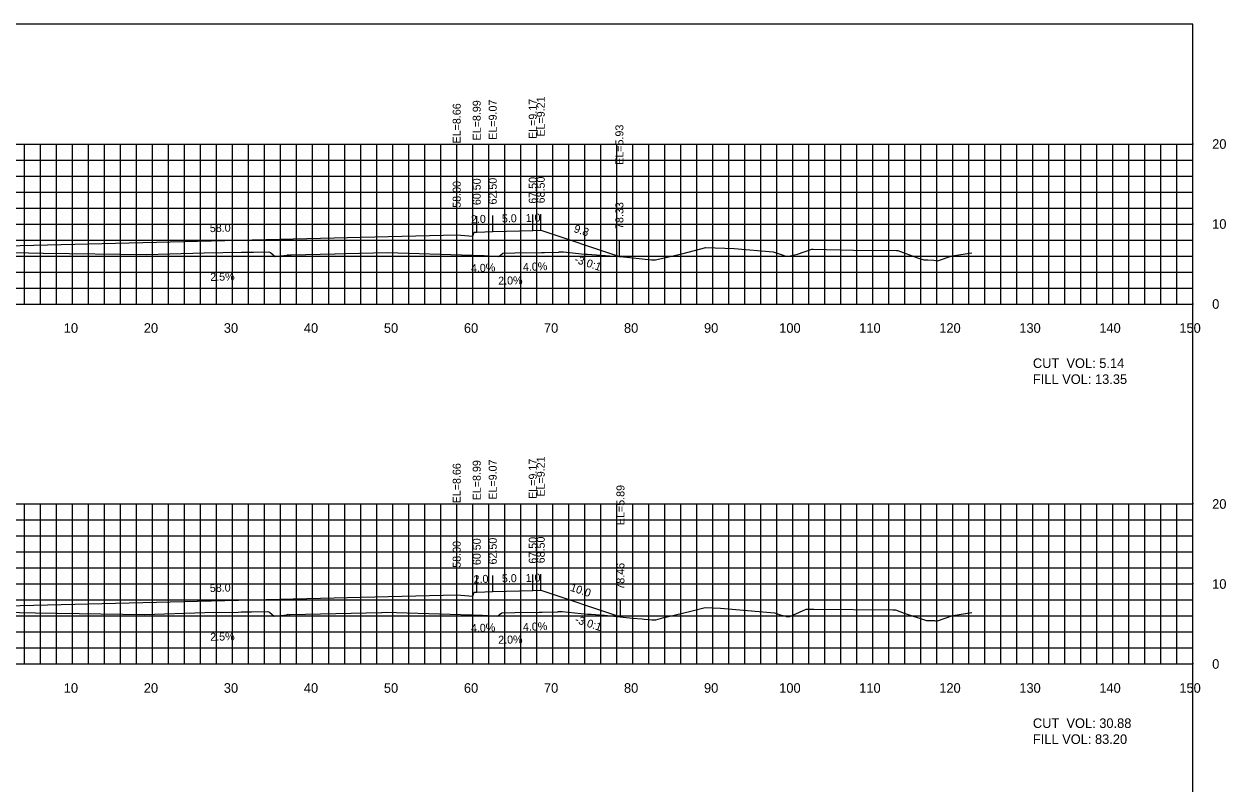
# Model space of a CAD drawing. Extents: x 1797419 to 1809236, y 248759 to 251512.
# Drawn here: x 1807054.9 to 1807205.1, y 250949.9 to 251044.9 of the extents above; entities that cross this region are included whole.
import ezdxf

# ---------------------------------------------------------------- set-up
doc = ezdxf.new("R2010")
doc.units = 0
for name, color, linetype in [('10', 7, 'Continuous'), ('3', 7, 'Continuous'), ('31', 7, 'Continuous'), ('4', 7, 'Continuous'), ('60', 7, 'Continuous'), ('ANNO-TXT', 7, 'Continuous'), ('CL-CNST', 7, 'Continuous'), ('Level 62', 7, 'Continuous'), ('M-ROADS', 7, 'Continuous')]:
    doc.layers.add(name, color=color, linetype=linetype)

msp = doc.modelspace()

# ---------------------------------------------------------------- linework, layer by layer
for p, q in [((1807109, 251018.55), (1807109, 251020.55)), ((1807111.5, 251018.88), (1807111.5, 251020.88)), ((1807113.5, 251018.96), (1807113.5, 251020.96)), ((1807118.5, 251019.06), (1807118.5, 251021.06)), ((1807119.5, 251019.1), (1807119.5, 251021.1)), ((1807129.33, 251015.82), (1807129.33, 251017.82)), ((1807109, 250973.55), (1807109, 250975.55)), ((1807111.5, 250973.88), (1807111.5, 250975.88)), ((1807113.5, 250973.96), (1807113.5, 250975.96)), ((1807118.5, 250974.06), (1807118.5, 250976.06)), ((1807119.5, 250974.1), (1807119.5, 250976.1)), ((1807129.46, 250970.78), (1807129.46, 250972.78))]:
    msp.add_line(p, q)
msp.add_lwpolyline([(1806901, 250854.89), (1807201, 250854.89), (1807201, 251044.89), (1806901, 251044.89)], close=True)
at = {"layer": '60'}
for p, q in [((1807201, 251009.89), (1807201, 251029.89)), ((1807201.06, 251029.89), (1807201, 251029.89)), ((1807201.06, 251019.89), (1807201, 251019.89)), ((1806901, 251009.89), (1807201, 251009.89)), ((1807061, 251009.83), (1807061, 251009.89)), ((1807071, 251009.83), (1807071, 251009.89)), ((1807081, 251009.83), (1807081, 251009.89)), ((1807091, 251009.83), (1807091, 251009.89)), ((1807101, 251009.83), (1807101, 251009.89)), ((1807111, 251009.83), (1807111, 251009.89)), ((1807121, 251009.83), (1807121, 251009.89)), ((1807131, 251009.83), (1807131, 251009.89)), ((1807141, 251009.83), (1807141, 251009.89)), ((1807151, 251009.83), (1807151, 251009.89)), ((1807161, 251009.83), (1807161, 251009.89)), ((1807171, 251009.83), (1807171, 251009.89)), ((1807181, 251009.83), (1807181, 251009.89)), ((1807191, 251009.83), (1807191, 251009.89)), ((1807201, 251009.83), (1807201, 251009.89)), ((1807201.06, 251009.89), (1807201, 251009.89)), ((1807201, 250964.89), (1807201, 250984.89)), ((1807201.06, 250984.89), (1807201, 250984.89)), ((1807201.06, 250974.89), (1807201, 250974.89)), ((1806901, 250964.89), (1807201, 250964.89)), ((1807061, 250964.83), (1807061, 250964.89)), ((1807071, 250964.83), (1807071, 250964.89)), ((1807081, 250964.83), (1807081, 250964.89)), ((1807091, 250964.83), (1807091, 250964.89)), ((1807101, 250964.83), (1807101, 250964.89)), ((1807111, 250964.83), (1807111, 250964.89)), ((1807121, 250964.83), (1807121, 250964.89)), ((1807131, 250964.83), (1807131, 250964.89)), ((1807141, 250964.83), (1807141, 250964.89)), ((1807151, 250964.83), (1807151, 250964.89)), ((1807161, 250964.83), (1807161, 250964.89)), ((1807171, 250964.83), (1807171, 250964.89)), ((1807181, 250964.83), (1807181, 250964.89)), ((1807191, 250964.83), (1807191, 250964.89)), ((1807201, 250964.83), (1807201, 250964.89)), ((1807201.06, 250964.89), (1807201, 250964.89))]:
    msp.add_line(p, q, dxfattribs=at)
at = {"layer": 'CL-CNST'}
for points in [[(1806978.72, 251017.46), (1806982.5, 251016.2), (1806983.5, 251016.16), (1806988.5, 251016.06), (1806990.5, 251015.98), (1806990.83, 251015.98), (1806991, 251015.48), (1806993, 251015.65), (1807051, 251017.1), (1807109, 251018.55), (1807111, 251018.38), (1807111.17, 251018.88), (1807111.5, 251018.88), (1807113.5, 251018.96), (1807118.5, 251019.06), (1807119.5, 251019.1), (1807129.33, 251015.82)], [(1806978.78, 250972.44), (1806982.5, 250971.2), (1806983.5, 250971.16), (1806988.5, 250971.06), (1806990.5, 250970.98), (1806990.83, 250970.98), (1806991, 250970.48), (1806993, 250970.65), (1807051, 250972.1), (1807109, 250973.55), (1807111, 250973.38), (1807111.17, 250973.88), (1807111.5, 250973.88), (1807113.5, 250973.96), (1807118.5, 250974.06), (1807119.5, 250974.1), (1807129.46, 250970.78)]]:
    msp.add_lwpolyline(points, dxfattribs=at)
at = {"layer": 'Level 62'}
for p, q in [((1806901, 251029.89), (1807201, 251029.89)), ((1807055, 251009.89), (1807055, 251029.89)), ((1807057, 251009.89), (1807057, 251029.89)), ((1807059, 251009.89), (1807059, 251029.89)), ((1807061, 251009.89), (1807061, 251029.89)), ((1807063, 251009.89), (1807063, 251029.89)), ((1807065, 251009.89), (1807065, 251029.89)), ((1807067, 251009.89), (1807067, 251029.89)), ((1807069, 251009.89), (1807069, 251029.89)), ((1807071, 251009.89), (1807071, 251029.89)), ((1807073, 251009.89), (1807073, 251029.89)), ((1807075, 251009.89), (1807075, 251029.89)), ((1807077, 251009.89), (1807077, 251029.89)), ((1807079, 251009.89), (1807079, 251029.89)), ((1807081, 251009.89), (1807081, 251029.89)), ((1807083, 251009.89), (1807083, 251029.89)), ((1807085, 251009.89), (1807085, 251029.89)), ((1807087, 251009.89), (1807087, 251029.89)), ((1807089, 251009.89), (1807089, 251029.89)), ((1807091, 251009.89), (1807091, 251029.89)), ((1807093, 251009.89), (1807093, 251029.89)), ((1807095, 251009.89), (1807095, 251029.89)), ((1807097, 251009.89), (1807097, 251029.89)), ((1807099, 251009.89), (1807099, 251029.89)), ((1807101, 251009.89), (1807101, 251029.89)), ((1807103, 251009.89), (1807103, 251029.89)), ((1807105, 251009.89), (1807105, 251029.89)), ((1807107, 251009.89), (1807107, 251029.89)), ((1807109, 251009.89), (1807109, 251029.89)), ((1807111, 251009.89), (1807111, 251029.89)), ((1807113, 251009.89), (1807113, 251029.89)), ((1807115, 251009.89), (1807115, 251029.89)), ((1807117, 251009.89), (1807117, 251029.89)), ((1807119, 251009.89), (1807119, 251029.89)), ((1807121, 251009.89), (1807121, 251029.89)), ((1807123, 251009.89), (1807123, 251029.89)), ((1807125, 251009.89), (1807125, 251029.89)), ((1807127, 251009.89), (1807127, 251029.89)), ((1807129, 251009.89), (1807129, 251029.89)), ((1807131, 251009.89), (1807131, 251029.89)), ((1807133, 251009.89), (1807133, 251029.89)), ((1807135, 251009.89), (1807135, 251029.89)), ((1807137, 251009.89), (1807137, 251029.89)), ((1807139, 251009.89), (1807139, 251029.89)), ((1807141, 251009.89), (1807141, 251029.89)), ((1807143, 251009.89), (1807143, 251029.89)), ((1807145, 251009.89), (1807145, 251029.89)), ((1807147, 251009.89), (1807147, 251029.89)), ((1807149, 251009.89), (1807149, 251029.89)), ((1807151, 251009.89), (1807151, 251029.89)), ((1807153, 251009.89), (1807153, 251029.89)), ((1807155, 251009.89), (1807155, 251029.89)), ((1807157, 251009.89), (1807157, 251029.89)), ((1807159, 251009.89), (1807159, 251029.89)), ((1807161, 251009.89), (1807161, 251029.89)), ((1807163, 251009.89), (1807163, 251029.89)), ((1807165, 251009.89), (1807165, 251029.89)), ((1807167, 251009.89), (1807167, 251029.89)), ((1807169, 251009.89), (1807169, 251029.89)), ((1807171, 251009.89), (1807171, 251029.89)), ((1807173, 251009.89), (1807173, 251029.89)), ((1807175, 251009.89), (1807175, 251029.89)), ((1807177, 251009.89), (1807177, 251029.89)), ((1807179, 251009.89), (1807179, 251029.89)), ((1807181, 251009.89), (1807181, 251029.89)), ((1807183, 251009.89), (1807183, 251029.89)), ((1807185, 251009.89), (1807185, 251029.89)), ((1807187, 251009.89), (1807187, 251029.89)), ((1807189, 251009.89), (1807189, 251029.89)), ((1807191, 251009.89), (1807191, 251029.89)), ((1807193, 251009.89), (1807193, 251029.89)), ((1807195, 251009.89), (1807195, 251029.89)), ((1807197, 251009.89), (1807197, 251029.89)), ((1807199, 251009.89), (1807199, 251029.89)), ((1807201, 251009.89), (1807201, 251029.89)), ((1806901, 251027.89), (1807201, 251027.89)), ((1806901, 251025.89), (1807201, 251025.89)), ((1806901, 251023.89), (1807201, 251023.89)), ((1806901, 251021.89), (1807201, 251021.89)), ((1806901, 251019.89), (1807201, 251019.89)), ((1806901, 251017.89), (1807201, 251017.89)), ((1806901, 251015.89), (1807201, 251015.89)), ((1806901, 251013.89), (1807201, 251013.89)), ((1806901, 251011.89), (1807201, 251011.89)), ((1806901, 251009.89), (1807201, 251009.89)), ((1806901, 250984.89), (1807201, 250984.89)), ((1807055, 250964.89), (1807055, 250984.89)), ((1807057, 250964.89), (1807057, 250984.89)), ((1807059, 250964.89), (1807059, 250984.89)), ((1807061, 250964.89), (1807061, 250984.89)), ((1807063, 250964.89), (1807063, 250984.89)), ((1807065, 250964.89), (1807065, 250984.89)), ((1807067, 250964.89), (1807067, 250984.89)), ((1807069, 250964.89), (1807069, 250984.89)), ((1807071, 250964.89), (1807071, 250984.89)), ((1807073, 250964.89), (1807073, 250984.89)), ((1807075, 250964.89), (1807075, 250984.89)), ((1807077, 250964.89), (1807077, 250984.89)), ((1807079, 250964.89), (1807079, 250984.89)), ((1807081, 250964.89), (1807081, 250984.89)), ((1807083, 250964.89), (1807083, 250984.89)), ((1807085, 250964.89), (1807085, 250984.89)), ((1807087, 250964.89), (1807087, 250984.89)), ((1807089, 250964.89), (1807089, 250984.89)), ((1807091, 250964.89), (1807091, 250984.89)), ((1807093, 250964.89), (1807093, 250984.89)), ((1807095, 250964.89), (1807095, 250984.89)), ((1807097, 250964.89), (1807097, 250984.89)), ((1807099, 250964.89), (1807099, 250984.89)), ((1807101, 250964.89), (1807101, 250984.89)), ((1807103, 250964.89), (1807103, 250984.89)), ((1807105, 250964.89), (1807105, 250984.89)), ((1807107, 250964.89), (1807107, 250984.89)), ((1807109, 250964.89), (1807109, 250984.89)), ((1807111, 250964.89), (1807111, 250984.89)), ((1807113, 250964.89), (1807113, 250984.89)), ((1807115, 250964.89), (1807115, 250984.89)), ((1807117, 250964.89), (1807117, 250984.89)), ((1807119, 250964.89), (1807119, 250984.89)), ((1807121, 250964.89), (1807121, 250984.89)), ((1807123, 250964.89), (1807123, 250984.89)), ((1807125, 250964.89), (1807125, 250984.89)), ((1807127, 250964.89), (1807127, 250984.89)), ((1807129, 250964.89), (1807129, 250984.89)), ((1807131, 250964.89), (1807131, 250984.89)), ((1807133, 250964.89), (1807133, 250984.89)), ((1807135, 250964.89), (1807135, 250984.89)), ((1807137, 250964.89), (1807137, 250984.89)), ((1807139, 250964.89), (1807139, 250984.89)), ((1807141, 250964.89), (1807141, 250984.89)), ((1807143, 250964.89), (1807143, 250984.89)), ((1807145, 250964.89), (1807145, 250984.89)), ((1807147, 250964.89), (1807147, 250984.89)), ((1807149, 250964.89), (1807149, 250984.89)), ((1807151, 250964.89), (1807151, 250984.89)), ((1807153, 250964.89), (1807153, 250984.89)), ((1807155, 250964.89), (1807155, 250984.89)), ((1807157, 250964.89), (1807157, 250984.89)), ((1807159, 250964.89), (1807159, 250984.89)), ((1807161, 250964.89), (1807161, 250984.89)), ((1807163, 250964.89), (1807163, 250984.89)), ((1807165, 250964.89), (1807165, 250984.89)), ((1807167, 250964.89), (1807167, 250984.89)), ((1807169, 250964.89), (1807169, 250984.89)), ((1807171, 250964.89), (1807171, 250984.89)), ((1807173, 250964.89), (1807173, 250984.89)), ((1807175, 250964.89), (1807175, 250984.89)), ((1807177, 250964.89), (1807177, 250984.89)), ((1807179, 250964.89), (1807179, 250984.89)), ((1807181, 250964.89), (1807181, 250984.89)), ((1807183, 250964.89), (1807183, 250984.89)), ((1807185, 250964.89), (1807185, 250984.89)), ((1807187, 250964.89), (1807187, 250984.89)), ((1807189, 250964.89), (1807189, 250984.89)), ((1807191, 250964.89), (1807191, 250984.89)), ((1807193, 250964.89), (1807193, 250984.89)), ((1807195, 250964.89), (1807195, 250984.89)), ((1807197, 250964.89), (1807197, 250984.89)), ((1807199, 250964.89), (1807199, 250984.89)), ((1807201, 250964.89), (1807201, 250984.89)), ((1806901, 250982.89), (1807201, 250982.89)), ((1806901, 250980.89), (1807201, 250980.89)), ((1806901, 250978.89), (1807201, 250978.89)), ((1806901, 250976.89), (1807201, 250976.89)), ((1806901, 250974.89), (1807201, 250974.89)), ((1806901, 250972.89), (1807201, 250972.89)), ((1806901, 250970.89), (1807201, 250970.89)), ((1806901, 250968.89), (1807201, 250968.89)), ((1806901, 250966.89), (1807201, 250966.89)), ((1806901, 250964.89), (1807201, 250964.89))]:
    msp.add_line(p, q, dxfattribs=at)
at = {"layer": 'M-ROADS'}
for points in [[(1807025.82, 251016.94), (1807057.34, 251016.26), (1807070.29, 251016.08), (1807077.43, 251016.29), (1807082.09, 251016.36), (1807082.16, 251016.37), (1807082.28, 251016.36), (1807082.28, 251016.36), (1807082.76, 251016.36), (1807082.77, 251016.36), (1807083.62, 251016.35), (1807085.51, 251016.4), (1807085.72, 251016.32), (1807086.06, 251016.02), (1807086.3, 251015.84), (1807087.76, 251016), (1807087.8, 251016.01), (1807087.84, 251016.02), (1807087.91, 251016.05), (1807087.99, 251016.03), (1807088.01, 251016.02), (1807088.1, 251016), (1807088.11, 251016), (1807088.22, 251016.03), (1807088.27, 251016.05), (1807088.3, 251016.05), (1807093.78, 251016.16), (1807093.81, 251016.16), (1807095.14, 251016.19), (1807100.32, 251016.31), (1807110.92, 251016), (1807112.33, 251015.95), (1807112.34, 251015.95), (1807112.39, 251015.95), (1807112.43, 251015.94), (1807114.24, 251015.81), (1807114.46, 251016), (1807114.75, 251016.26), (1807116.27, 251016.29), (1807119.6, 251016.33), (1807119.64, 251016.33), (1807119.88, 251016.33), (1807119.96, 251016.32), (1807121.74, 251016.35), (1807121.77, 251016.35), (1807121.79, 251016.4), (1807122.24, 251016.41), (1807122.33, 251016.4), (1807124.97, 251016.13), (1807125.35, 251016.13), (1807129.26, 251015.83), (1807129.46, 251015.81), (1807133.36, 251015.42), (1807133.73, 251015.42), (1807133.84, 251015.42), (1807137.12, 251016.18), (1807140.13, 251016.94), (1807143.65, 251016.84), (1807148.56, 251016.41), (1807149.66, 251016.04), (1807150.14, 251015.86), (1807150.51, 251015.86), (1807151.6, 251016.12), (1807153.37, 251016.74), (1807153.55, 251016.74), (1807158.57, 251016.64), (1807163.95, 251016.59), (1807164.12, 251016.59), (1807166.56, 251015.67), (1807167.36, 251015.41), (1807167.43, 251015.41), (1807167.86, 251015.41), (1807168.6, 251015.37), (1807168.64, 251015.37), (1807169.06, 251015.27), (1807170.91, 251015.92), (1807173.37, 251016.28)], [(1807026.64, 250971.92), (1807056.38, 250971.28), (1807070, 250971.09), (1807077.52, 250971.31), (1807081.71, 250971.38), (1807082.06, 250971.4), (1807082.15, 250971.4), (1807082.25, 250971.4), (1807082.64, 250971.4), (1807082.66, 250971.4), (1807083.36, 250971.39), (1807085.38, 250971.44), (1807085.61, 250971.36), (1807085.93, 250971.07), (1807086.19, 250970.88), (1807087.76, 250971.05), (1807087.8, 250971.06), (1807087.84, 250971.07), (1807087.92, 250971.1), (1807088.01, 250971.08), (1807088.03, 250971.07), (1807088.12, 250971.05), (1807088.13, 250971.05), (1807088.18, 250971.06), (1807088.18, 250971.06), (1807099.59, 250971.34), (1807099.64, 250971.34), (1807100.19, 250971.36), (1807101.48, 250971.32), (1807112.21, 250970.98), (1807112.23, 250970.98), (1807114.12, 250970.85), (1807114.35, 250971.06), (1807114.63, 250971.3), (1807116.26, 250971.33), (1807119.3, 250971.36), (1807119.34, 250971.36), (1807119.6, 250971.36), (1807119.68, 250971.36), (1807121.62, 250971.39), (1807121.65, 250971.39), (1807121.66, 250971.43), (1807122.09, 250971.44), (1807122.18, 250971.44), (1807125.36, 250971.11), (1807125.81, 250971.11), (1807127.38, 250970.99), (1807127.46, 250970.98), (1807130.98, 250970.63), (1807132.19, 250970.52), (1807132.42, 250970.5), (1807133.39, 250970.42), (1807133.41, 250970.42), (1807133.9, 250970.42), (1807134.48, 250970.59), (1807134.99, 250970.74), (1807135.13, 250970.75), (1807138.43, 250971.52), (1807140.06, 250971.93), (1807141.96, 250971.88), (1807148.7, 250971.28), (1807149.65, 250970.96), (1807149.8, 250970.97), (1807150.14, 250970.85), (1807150.18, 250970.83), (1807150.2, 250970.83), (1807150.64, 250970.83), (1807151.02, 250970.98), (1807152.68, 250971.75), (1807152.69, 250971.75), (1807152.71, 250971.75), (1807153.09, 250971.75), (1807153.2, 250971.75), (1807153.64, 250971.75), (1807163.49, 250971.66), (1807163.82, 250971.66), (1807164.93, 250971.24), (1807167.72, 250970.34), (1807167.99, 250970.34), (1807168.23, 250970.33), (1807168.64, 250970.31), (1807168.7, 250970.32), (1807168.95, 250970.26), (1807170.98, 250970.97), (1807173.35, 250971.32)]]:
    msp.add_lwpolyline(points, dxfattribs=at)

# ---------------------------------------------------------------- texts
for p in [(1807123.63, 251015.09), (1807123.69, 250970.07)]:
    msp.add_text('-3.0:1', height=1, rotation=341.5651).set_placement(p)
at = {"layer": '10'}
for s, p in [('10', (1807059.9, 251006.29)), ('20', (1807069.9, 251006.29)), ('30', (1807079.9, 251006.29)), ('40', (1807089.9, 251006.29)), ('50', (1807099.9, 251006.29)), ('60', (1807109.9, 251006.29)), ('70', (1807119.9, 251006.29)), ('80', (1807129.9, 251006.29)), ('90', (1807139.9, 251006.29)), ('100', (1807149.3, 251006.29)), ('110', (1807159.3, 251006.29)), ('120', (1807169.3, 251006.29)), ('130', (1807179.3, 251006.29)), ('140', (1807189.3, 251006.29)), ('150', (1807199.3, 251006.29)), ('10', (1807059.9, 250961.29)), ('20', (1807069.9, 250961.29)), ('30', (1807079.9, 250961.29)), ('40', (1807089.9, 250961.29)), ('50', (1807099.9, 250961.29)), ('60', (1807109.9, 250961.29)), ('70', (1807119.9, 250961.29)), ('80', (1807129.9, 250961.29)), ('90', (1807139.9, 250961.29)), ('100', (1807149.3, 250961.29)), ('110', (1807159.3, 250961.29)), ('120', (1807169.3, 250961.29)), ('130', (1807179.3, 250961.29)), ('140', (1807189.3, 250961.29)), ('150', (1807199.3, 250961.29))]:
    msp.add_text(s, height=1.2, dxfattribs=at).set_placement(p)
at = {"layer": '3'}
for s, p in [('EL=8.99', (1807112, 251030.34)), ('EL=9.07', (1807114, 251030.42)), ('EL=9.17', (1807119, 251030.52)), ('EL=9.21', (1807120, 251030.82)), ('EL=8.66', (1807109.5, 251029.96)), ('EL=5.93', (1807129.83, 251027.29)), ('58.00', (1807109.5, 251021.92)), ('60.50', (1807112, 251022.25)), ('62.50', (1807114, 251022.33)), ('67.50', (1807119, 251022.43)), ('68.50', (1807120, 251022.47)), ('78.33', (1807129.83, 251019.27)), ('EL=8.99', (1807112, 250985.35)), ('EL=9.07', (1807114, 250985.43)), ('EL=9.17', (1807119, 250985.53)), ('EL=9.21', (1807120, 250985.82)), ('EL=8.66', (1807109.5, 250984.97)), ('EL=5.89', (1807129.96, 250982.25)), ('58.00', (1807109.5, 250976.92)), ('60.50', (1807112, 250977.25)), ('62.50', (1807114, 250977.33)), ('67.50', (1807119, 250977.43)), ('68.50', (1807120, 250977.47)), ('78.46', (1807129.96, 250974.18))]:
    msp.add_text(s, height=1, rotation=90, dxfattribs=at).set_placement(p)
at = {"layer": '31'}
for s, p in [('20', (1807203.4, 251029.29)), ('10', (1807203.4, 251019.29)), ('0', (1807203.4, 251009.29)), ('20', (1807203.4, 250984.29)), ('10', (1807203.4, 250974.29)), ('0', (1807203.4, 250964.29))]:
    msp.add_text(s, height=1.2, dxfattribs=at).set_placement(p)
at = {"layer": '4'}
for s, rotation, p in [('2.0', 2.2906, (1807110.8, 251019.97)), ('5.0', 1.1458, (1807114.65, 251020.08)), ('1.0', 2.2906, (1807117.63, 251020.13)), ('58.0', 1.4321, (1807078.16, 251018.87)), ('9.8', 341.5651, (1807123.55, 251018.91)), ('4.0%', 2.2906, (1807110.79, 251013.85)), ('4.0%', 2.2906, (1807117.29, 251014.01)), ('2.5%', 1.4321, (1807078.21, 251012.77)), ('2.0%', 1.1458, (1807114.19, 251012.3)), ('2.0', 2.2906, (1807111.13, 250974.97)), ('5.0', 1.1458, (1807114.65, 250975.09)), ('1.0', 2.2906, (1807117.63, 250975.13)), ('58.0', 1.4321, (1807078.16, 250973.88)), ('10.0', 341.5651, (1807123.1, 250974.06)), ('4.0%', 2.2906, (1807110.79, 250968.85)), ('4.0%', 2.2906, (1807117.29, 250969.01)), ('2.5%', 1.4321, (1807078.21, 250967.78)), ('2.0%', 1.1458, (1807114.19, 250967.41))]:
    msp.add_text(s, height=1, rotation=rotation, dxfattribs=at).set_placement(p)
at = {"layer": 'ANNO-TXT'}
for s, p in [('CUT  VOL: 5.14', (1807181, 251001.89)), ('FILL VOL: 13.35', (1807181, 250999.89)), ('CUT  VOL: 30.88', (1807181, 250956.89)), ('FILL VOL: 83.20', (1807181, 250954.89))]:
    msp.add_text(s, height=1.2, dxfattribs=at).set_placement(p)

doc.saveas('drawing.dxf')
